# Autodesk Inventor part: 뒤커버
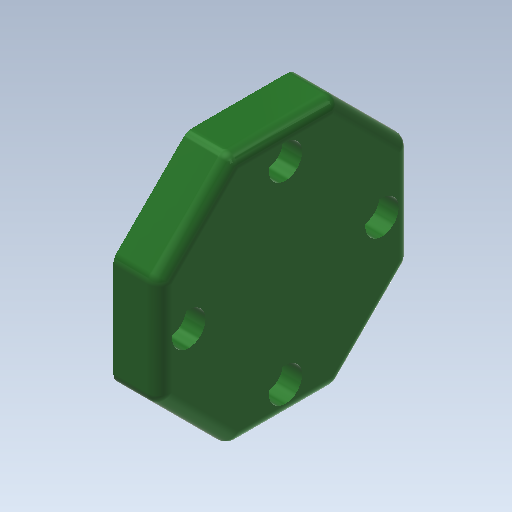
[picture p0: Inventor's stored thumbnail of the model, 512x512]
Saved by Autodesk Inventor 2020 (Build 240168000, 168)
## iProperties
Created: 2015-11
Part Number: 뒤커버
Material: 알루미늄 6061
Document SubType Name: Modeling
Designer: mduedu
Density: 1 g/cm^3
Appearance: 매끄러움 - 짙은 산림 녹색
Author: mduedu
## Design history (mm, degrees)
sketch "스케치5" dims "d66" = 60
  geometry: L1 (12.426, 30)-(30, 12.426); L2 (30, 12.426)-(30, -12.426); L3 (30, -12.426)-(12.426, -30); L4 (12.426, -30)-(-12.426, -30); L5 (-12.426, -30)-(-30, -12.426); L6 (-30, -12.426)-(-30, 12.426); L7 (-30, 12.426)-(-12.426, 30); L8 (-12.426, 30)-(12.426, 30); 4 further points
  constraints: 16 end point, 2 coincident, 2 vertical alignment, 1 midpoint, 19 other
extrude "돌출2" new body sketch "스케치5" distance "d67" = 11; taper "d68" = 0 deg
sketch "스케치6"
  geometry: C1 r 16 at (0, 0); 1 further point
  constraints: 1 centre point, 1 coincident
  dimensions: "d69" = 32 diameter of C1
extrude "돌출3" join sketch "스케치6" distance "d70" = 3; taper "d71" = 0 deg
hole "구멍5" diameter "d74" = 25; stored, may be unused: countersink angle "d78" = 90 deg, drill point angle "d80" = 0 deg; dims "d72" = 10, "d73" = 10, "d75" = 6, "d76" = 4, "d77" = 2, "d79" = 10
fillet "모깎기7" dims "d81" = 3
fillet "모깎기8" dims "d82" = 3
fillet "모깎기9" dims "d83" = 3
fillet "모깎기10" dims "d84" = 0.3
sketch "스케치7" dims "d85" = 46
  geometry: 3 further points
  constraints: 2 vertical alignment, 1 coincident, 2 other
hole "구멍6" sketch "스케치7" at (0, 23) diameter "d86" = 4.5; stored, may be unused: countersink angle "d90" = 90 deg, drill point angle "d92" = 0 deg; dims "d87" = 6, "d88" = 8, "d89" = 4.6, "d91" = 10
node "솔리드2"
pattern_circular "원형 패턴3" dims angle "d94" = 360 deg
